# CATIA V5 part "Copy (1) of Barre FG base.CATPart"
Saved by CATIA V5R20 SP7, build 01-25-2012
Part number: Copy (1) of Barre FG base
Bounding box of the stored display mesh (mm): x -3 to 3, y -19.215 to 15.78, z 15.685 to 43.054
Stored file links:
  U:\IAO_bon\Copy (1) of Barre FG base.CATPart
  U:\IAO_bon\Cqueguiner_IAo.CATProduct
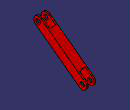
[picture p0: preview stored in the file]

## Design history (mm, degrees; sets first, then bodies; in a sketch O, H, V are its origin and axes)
Set1
  Point1 "Point F": linked copy from another document
  Point2 "Point B/G": linked copy from another document
Set2
  Plane1: type Offset, RefPlane face of Pad1 from Sketch1.L1, Offset -3, reversed
Body1 (main body)
  Sketch1 on yz-plane, origin (0, 0, 0), H (0, 1, 0), V (0, 0, 1)
    line L1 (-14.454, 42.4759) -> (14.5773, 21.0941)
    arc A1 centre (12.7983, 18.6785) radius 3 from (14.5773, 21.0941) to (11.0192, 16.263) cw
    point P3 (12.7983, 18.6785)
    line L2 (11.0192, 16.263) -> (-18.0121, 37.6448)
    arc A2 centre (-16.2331, 40.0604) radius 3 from (-18.0121, 37.6448) to (-14.454, 42.4759) cw
    point P6 (-16.2331, 40.0604)
    reference projected point E1 (-16.2331, 40.0604) from Point1
    reference projected point E2 (12.7983, 18.6785) from Point2
    circle A3 centre (12.7983, 18.6785) radius 1.5
    circle A4 centre (-16.2331, 40.0604) radius 1.5
    distance L2 L1 = 6
    radius A3 = 1.5
    radius A4 = 1.5
    tangency: A1 L1, L2 A1, A2 L1, A2 L2
    coincidence: P6 E1, P3 E2
  Pad1: profile Sketch1, direction (1, 0, 0), length 3, opposite side length 3
  Sketch2 on face of Pad1 from Sketch1.L1, origin (0, 15.1988, 20.6363), H (-1, 0, 0), V (0, -0.8052, 0.593)
    line L1 (-2, 6.7719) -> (2, 6.7719)
    line L2 (2, 6.7719) -> (2, -4.2281)
    line L3 (2, -4.2281) -> (-2, -4.2281)
    line L4 (-2, -4.2281) -> (-2, 6.7719)
    reference projected line E1 through (0, 0.7719) direction (-1, 0) from axis of face of Pad1 from Sketch1.A1
    length L1 = 4
    length L2 = 11
    distance E1 L1 = 6
    horizontal: L1 H, L3 H
    vertical: L2 V, L4 V
  Pocket1: profile Sketch2, direction (0, -0.593, -0.8052), through (limit type 6)
  Sketch3 on face of Pad1 from Sketch1.L1, origin (0, 15.1988, 20.6363), H (-1, 0, 0), V (0, -0.8052, 0.593)
    line L1 (-2, 40.8274) -> (2, 40.8274)
    line L2 (2, 40.8274) -> (2, 30.8274)
    line L3 (2, 30.8274) -> (-2, 30.8274)
    line L4 (-2, 30.8274) -> (-2, 40.8274)
    reference projected line E1 through (0, 36.8274) direction (-1, 0) from axis of face of Pad1 from Sketch1.A2
    length L3 = 4
    length L2 = 10
    distance E1 L3 = 6
    horizontal: L1 H, L3 H
    vertical: L2 V, L4 V
  Pocket2: profile Sketch3, direction (0, -0.593, -0.8052), through (limit type 6)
